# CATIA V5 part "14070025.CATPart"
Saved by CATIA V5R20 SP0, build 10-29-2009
Part number: 14070025
Definition: NONE
Nomenclature: 14070025
Source: Unknown
Description: 14070025
Bounding box of the stored display mesh (mm): x -12.5 to 50, y -49 to 39.1, z -39.1 to 39.1
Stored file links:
  C:\Users\Utente\Desktop\IO LAVORO\3D X SITO CF\X SITO\PLASTICA\RF2\14070025.CATPart
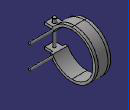
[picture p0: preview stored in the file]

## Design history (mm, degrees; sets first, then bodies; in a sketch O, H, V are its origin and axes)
Body1 "14070025" (main body)
  Solid1: solid without history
